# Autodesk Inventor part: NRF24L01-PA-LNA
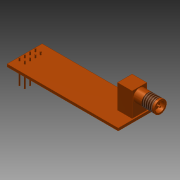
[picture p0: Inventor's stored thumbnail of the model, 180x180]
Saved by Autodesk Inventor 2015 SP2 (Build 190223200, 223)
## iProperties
Created: 2015-09
Part Number: NRF24L01-PA-LNA
Material: Phenolharz
Document SubType Name: Modeling
Designer: rYan
Mass: 2.77005 g
Surface Area: 26.9268 cm^2
Volume: 2.00728 cm^3
Density: 1.38 g/cm^3
Appearance: Glatt - hellorange
Author: rYan
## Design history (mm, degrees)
sketch "Skizze1"
  geometry: L1 (-26.65, 8.4)-(26.65, 8.4); L2 (26.65, 8.4)-(26.65, -8.4); L3 (26.65, -8.4)-(-26.65, -8.4); L4 (-26.65, -8.4)-(-26.65, 8.4); L5 (0, 11.76)-(0, -11.76) reference; L6 (-37.31, 0)-(37.31, 0) reference; 1 further point
  constraints: 8 end point, 2 parallel, 1 horizontal, 1 perpendicular, 2 other
  dimensions: "d0" = 53.3 distance of L1.start L1.end; "d1" = 16.8 distance of L1.end L2.end
extrude "Extrusion1" new body sketch "Skizze1" distance "d2" = 1.2; taper "d3" = 0 deg
sketch "Skizze2"
  geometry: L1 (26.25, -5.4)-(23.71, -5.4); L2 (23.71, -5.4)-(23.71, -2.86); L3 (23.71, -2.86)-(26.25, -2.86); L4 (26.25, -2.86)-(26.25, -5.4); L5 (26.65, 8.4)-(-26.65, 8.4) reference; L6 (-26.65, 8.4)-(-26.65, -8.4) reference; L7 (-26.65, -8.4)-(26.65, -8.4) reference; L8 (26.65, -8.4)-(26.65, 8.4) reference; 1 further point
  constraints: 8 end point, 2 parallel, 1 horizontal, 1 perpendicular
  dimensions: "d4" = 2.54 distance of L1.start L1.end; "d5" = 2.54 distance of L1.end L2.end; "d6" = 3 distance between parallel lines of L7 L1; "d7" = 0.4 distance between parallel lines of L8 L4
extrude "Extrusion2" join sketch "Skizze2" distance "d8" = 2; taper "d9" = 0 deg
sketch "Skizze3"
  geometry: L1 (23.71, -5.4)-(26.25, -5.4) reference; L2 (26.25, -5.4)-(26.25, -2.86) reference; L3 (26.25, -2.86)-(23.71, -2.86) reference; L4 (23.71, -2.86)-(23.71, -5.4) reference; L5 (26.25, -5.4)-(23.71, -5.4) reference; L6 (24.98, -5.4)-(24.98, -2.86); L7 (26.25, -2.86)-(26.25, -5.4) reference; L8 (26.25, -4.13)-(23.71, -4.13); C1 r 0.3 at (24.98, -4.13); 1 further point
  constraints: 5 midpoint, 4 end point, 1 centre point
  dimensions: "d40" = 0.6 diameter of C1
extrude "Extrusion3" join sketch "Skizze3" distance "d12" = 7; taper "d13" = 0 deg; dims "d14" = 4.5, "d15" = 0
pattern_linear "Rechteckige Anordnung1" dims "d18" = 2.54, "d21" = 2.54
sketch "Skizze4"
  geometry: L1 (19.05, 5.86)-(26.05, 5.86); L2 (26.05, 5.86)-(26.05, -1.14); L3 (26.05, -1.14)-(19.05, -1.14); L4 (19.05, -1.14)-(19.05, 5.86); L5 (26.65, 8.4)-(-26.65, 8.4) reference; L6 (26.65, -8.4)-(26.65, 8.4) reference; 1 further point
  constraints: 8 end point, 2 parallel, 1 horizontal, 1 perpendicular
  dimensions: "d22" = 7 distance of L1.start L1.end; "d23" = 7 distance of L1.end L2.end; "d24" = 2.54 distance between parallel lines of L5 L1; "d25" = 0.6 distance between parallel lines of L6 L2
extrude "Extrusion4" join sketch "Skizze4" distance "d26" = 11.5; taper "d27" = 0 deg
sketch "Skizze5"
  geometry: L1 (0, 7)-(0, 0) reference; L2 (0, 7)-(-11.5, 7) reference; L3 (-11.5, 0)-(-11.5, 7) reference; L4 (0, 0)-(-11.5, 0) reference; L5 (-11.5, 7)-(-11.5, 0) reference; L6 (-11.5, 3.5)-(0, 3.5); L7 (0, 7)-(0, 0) reference; C1 r 3 at (-8.1, 3.5); 1 further point
  constraints: 2 end point, 2 midpoint, 1 centre point, 1 point on line
  dimensions: "d28" = 6 diameter of C1; "d29" = 3.4 distance from line of L3 C1.centre
extrude "Extrusion5" join sketch "Skizze5" distance "d30" = 10; taper "d31" = 0 deg
sketch "Skizze6"
  geometry: C1 r 3 at (0, 0) reference; C2 r 2.3 at (0, 0); 1 further point
  constraints: 1 centre point, 1 coincident
  dimensions: "d32" = 4.6 diameter of C2
extrude "Extrusion6" cut sketch "Skizze6" distance "d33" = 2.2; taper "d34" = 0 deg
sketch "Skizze7"
  geometry: C1 r 2.3 at (0, 0) reference; C2 r 0.45 at (0, 0); 1 further point
  constraints: 1 centre point, 1 coincident
  dimensions: "d35" = 0.9 diameter of C2
extrude "Extrusion7" join sketch "Skizze7" distance "d36" = 2.2; taper "d37" = -3 deg
feature "Gewinde1" dims "d38" = 5, "d39" = 1
node "Volumenkörper1"
node "Projizierte Kontur1"
node "Projizierte Kontur2"
node "Projizierte Kontur3"
node "Projizierte Kontur4"
node "Projizierte Kontur5"
